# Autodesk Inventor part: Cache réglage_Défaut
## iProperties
Shininess: 64.0
Length Units: 11269
Angle Units: 11279
Time Units: 11290
Mass Units: 11283
Length Display Precision: 3
Angle Display Precision: 2
Compacted: True
Part Number: Cache réglage_Défaut
Document SubType Name: Modeling
Created: 2006-01
Material: Par défaut
Designer: riri
Density: 0.0
Volumn: 0.0
Area: 0.0
PropertySet Name: Model Information
Control State: 0
Master: False
Checked Out: False
Author: riri
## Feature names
1. Base1
